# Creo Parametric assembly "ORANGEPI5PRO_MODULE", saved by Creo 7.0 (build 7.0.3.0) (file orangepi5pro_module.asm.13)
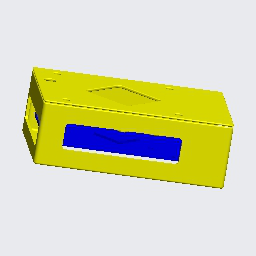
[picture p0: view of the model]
Units: millimeter Kilogram Sec (mmKs); MM, KILOGRAM, SECS

Created from: XX_MMKS_ASM_DESIGN_ABS.ASM

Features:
  1. datum plane "ASM_RIGHT"
  2. datum plane "ASM_TOP"
  3. datum plane "ASM_FRONT"
  4. coordinate system
  5. component "PI5PRO_BOX"
  6. component "ORANGEPI5PRO"
  7. component "FAN_SET"
  8. component "PI5PRO_COVER"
